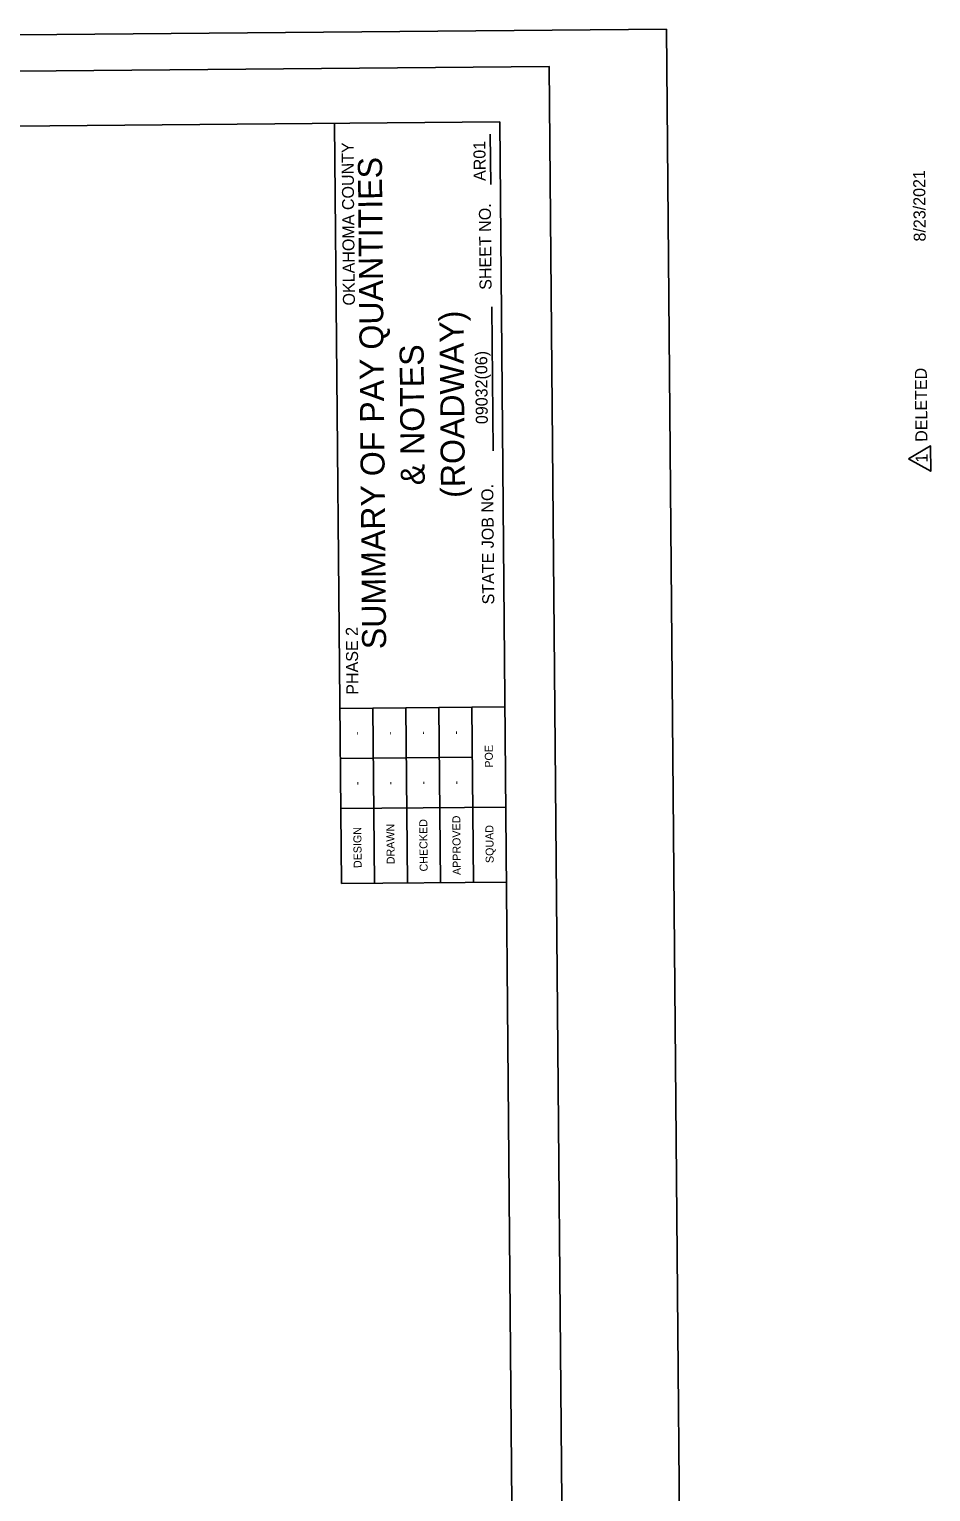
# Model space of a CAD drawing. Extents: x 2151899 to 2151927, y 142567 to 142686.
# Drawn here: x 2151918.41 to 2151927.42, y 142588.79 to 142603.41 of the extents above; entities that cross this region are included whole.
import ezdxf

# ---------------------------------------------------------------- set-up
doc = ezdxf.new("R2010")
doc.units = 0
for name, color, linetype in [('SHT_Plot_Shape_Full', 7, 'Continuous'), ('SHT_Plot_Shape_Half', 7, 'Continuous'), ('SHT_Sheet_Border', 7, 'Continuous'), ('SHT_Standard_Sheet_Lines', 7, 'Continuous'), ('SHT_Standard_Sheet_Txt', 7, 'Continuous'), ('TYP_Typical_Section_Txt', 7, 'Continuous')]:
    doc.layers.add(name, color=color, linetype=linetype)

msp = doc.modelspace()

# ---------------------------------------------------------------- linework, layer by layer
at = {"layer": 'SHT_Plot_Shape_Full'}
msp.add_lwpolyline([(2151901.092, 142567.2), (2151900.777, 142603.199), (2151924.776, 142603.409), (2151925.091, 142567.41)], close=True, dxfattribs=at)
at = {"layer": 'SHT_Plot_Shape_Half'}
msp.add_lwpolyline([(2151901.903, 142568.845), (2151901.605, 142602.844), (2151923.604, 142603.036), (2151923.902, 142569.037)], close=True, dxfattribs=at)
at = {"layer": 'SHT_Sheet_Border'}
for p, q in [((2151921.526, 142594.868), (2151921.459, 142602.467)), ((2151923.16, 142596.632), (2151921.51, 142596.617)), ((2151923.176, 142594.882), (2151921.526, 142594.868))]:
    msp.add_line(p, q, dxfattribs=at)
msp.add_lwpolyline([(2151923.385, 142570.983), (2151923.109, 142602.482), (2151902.11, 142602.298), (2151902.386, 142570.799)], close=True, dxfattribs=at)
at = {"layer": 'SHT_Standard_Sheet_Lines'}
for p, q in [((2151923.019, 142601.856), (2151923.014, 142602.359)), ((2151923.042, 142599.192), (2151923.029, 142600.632)), ((2151922.835, 142596.129), (2151921.514, 142596.118)), ((2151923.169, 142595.632), (2151921.518, 142595.618))]:
    msp.add_line(p, q, dxfattribs=at)
for points in [[(2151921.84, 142596.62), (2151921.856, 142594.871)], [(2151922.17, 142596.623), (2151922.186, 142594.873)], [(2151922.5, 142596.626), (2151922.516, 142594.876)], [(2151922.83, 142596.629), (2151922.846, 142594.879)]]:
    msp.add_lwpolyline(points, dxfattribs=at)
at = {"layer": 'TYP_Typical_Section_Txt'}
msp.add_lwpolyline([(2151927.197, 142599.114), (2151927.418, 142598.989), (2151927.416, 142599.243)], close=True, dxfattribs=at)

# ---------------------------------------------------------------- texts
at = {"layer": 'SHT_Standard_Sheet_Txt'}
for s, height, p in [('OKLAHOMA COUNTY', 0.12, (2151921.662, 142600.647)), ('AR01', 0.12, (2151922.969, 142601.892)), ('SUMMARY OF PAY QUANTITIES', 0.24, (2151921.974, 142597.211)), ('SHEET NO. ', 0.12, (2151923.028, 142600.804)), ('(ROADWAY)', 0.24, (2151922.762, 142598.724)), ('& NOTES', 0.24, (2151922.36, 142598.85)), ('09032(06)', 0.12, (2151922.99, 142599.461)), ('STATE JOB NO.', 0.12, (2151923.055, 142597.658)), ('PHASE 2', 0.12, (2151921.696, 142596.755)), ('-', 0.08, (2151921.717, 142596.35)), ('-', 0.08, (2151922.047, 142596.353)), ('-', 0.08, (2151922.377, 142596.356)), ('-', 0.08, (2151922.708, 142596.359)), ('POE', 0.08, (2151923.041, 142596.026)), ('-', 0.08, (2151921.721, 142595.85)), ('-', 0.08, (2151922.052, 142595.853)), ('-', 0.08, (2151922.382, 142595.856)), ('-', 0.08, (2151922.712, 142595.859)), ('CHECKED', 0.08, (2151922.389, 142594.988)), ('APPROVED', 0.08, (2151922.72, 142594.952)), ('DESIGN', 0.08, (2151921.729, 142595.022)), ('DRAWN', 0.08, (2151922.059, 142595.06)), ('SQUAD', 0.08, (2151923.049, 142595.072))]:
    msp.add_text(s, height=height, rotation=90.5015, dxfattribs=at).set_placement(p)
at = {"layer": 'TYP_Typical_Section_Txt'}
for s, p in [('8/23/2021', (2151927.368, 142601.287)), ('DELETED', (2151927.385, 142599.284)), ('1', (2151927.387, 142599.076))]:
    msp.add_text(s, height=0.12, rotation=90.5015, dxfattribs=at).set_placement(p)

doc.saveas('drawing.dxf')
